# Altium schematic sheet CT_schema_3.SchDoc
size 287 x 169 mm
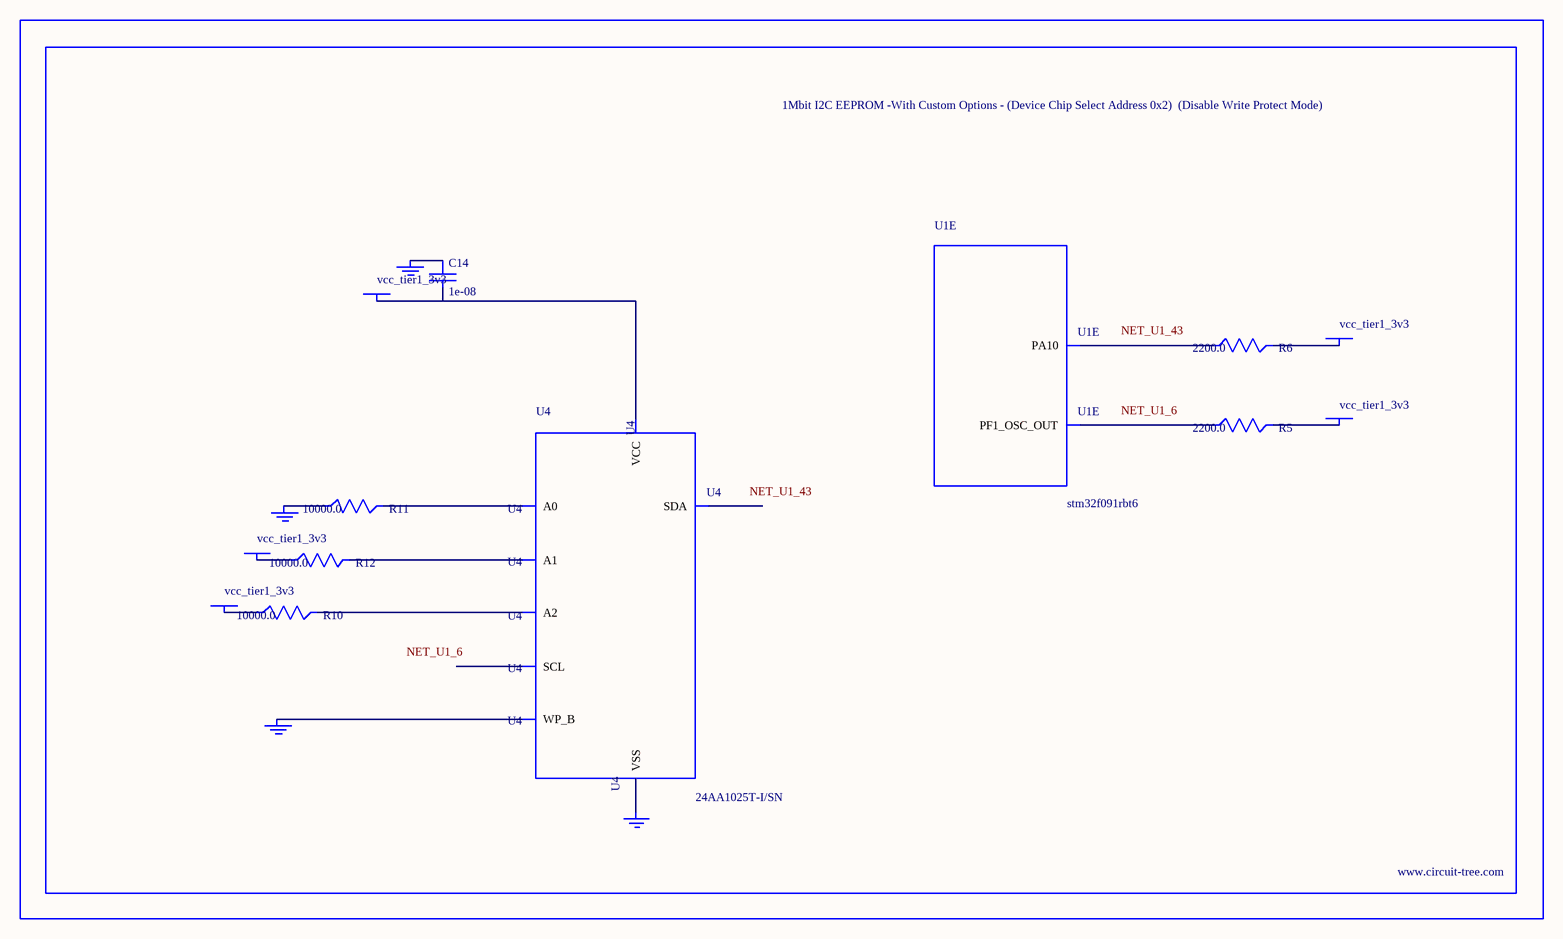
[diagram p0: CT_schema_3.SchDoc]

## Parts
BORDER2  (no value)
C14  1e-08  [C0402]
GND_INSTANCE_2_0  (no value)
GND_INSTANCE_2_1  (no value)
GND_INSTANCE_2_2  (no value)
GND_INSTANCE_2_3  (no value)
POWER_INSTANCE_2_0  vcc_tier1_3v3
POWER_INSTANCE_2_1  vcc_tier1_3v3
POWER_INSTANCE_2_2  vcc_tier1_3v3
POWER_INSTANCE_2_3  vcc_tier1_3v3
POWER_INSTANCE_2_4  vcc_tier1_3v3
R5  2200.0  [R0603]
R6  2200.0  [R0603]
R10  10000.0  [R0603]
R11  10000.0  [R0603]
R12  10000.0  [R0603]
U1  stm32f091rbt6  [LQFP64]  (part E of 6)
U4  24AA1025T-I/SN  [SOIC-8]

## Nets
NetC14_1: C14.1 GND_INSTANCE_2_2.0(GND)
NetC14_2: C14.2 POWER_INSTANCE_2_2.0(PWR) U4.8(VCC)
NetGND_INSTANCE_2_0_0: GND_INSTANCE_2_0.0(GND) R11.1
NetGND_INSTANCE_2_1_0: GND_INSTANCE_2_1.0(GND) U4.7(WP_B)
NetGND_INSTANCE_2_3_0: GND_INSTANCE_2_3.0(GND) U4.4(VSS)
NetPOWER_INSTANCE_2_0_0: POWER_INSTANCE_2_0.0(PWR) R12.1
NetPOWER_INSTANCE_2_1_0: POWER_INSTANCE_2_1.0(PWR) R10.1
NetPOWER_INSTANCE_2_3_0: POWER_INSTANCE_2_3.0(PWR) R5.2
NetPOWER_INSTANCE_2_4_0: POWER_INSTANCE_2_4.0(PWR) R6.2
NetR5_1: R5.1 U1.6(PF1_OSC_OUT)
NetR6_1: R6.1 U1.43(PA10)
NetR10_2: R10.2 U4.3(A2)
NetR11_2: R11.2 U4.1(A0)
NetR12_2: R12.2 U4.2(A1)

Not connected (* = marked no-connect by the designer): U4 5(SDA) 6(SCL)

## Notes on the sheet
- Labels drawn without touching a wire or pin: NET_U1_6, NET_U1_43

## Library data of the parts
BORDER2 = BORDER_PAGE2
C14 = C0402C103K3RAC
GND_INSTANCE_2_0-GND_INSTANCE_2_3 = GND
POWER_INSTANCE_2_0-POWER_INSTANCE_2_4 = PWR
R5 R6 = RC0603JR-072K2L
R10-R12 = RC0603JR-0710KL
